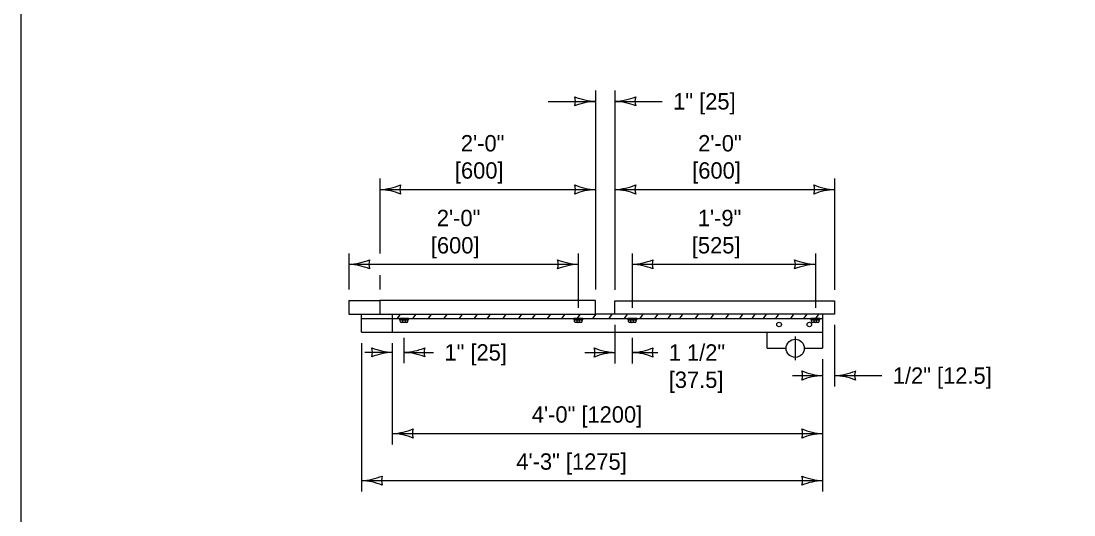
# Model space of a CAD drawing. Extents: x 49991.4 to 50021, y 49987.6 to 50011.4.
# Drawn here: x 49999.384 to 50003.247, y 49992.347 to 49994.159 of the extents above; entities that cross this region are included whole.
import ezdxf

# ---------------------------------------------------------------- set-up
doc = ezdxf.new("R2010")
doc.units = 0
for name, color, linetype in [('Level 1', 7, 'Continuous'), ('Level 2', 7, 'Continuous'), ('Level 3', 7, 'Continuous'), ('Level 4', 7, 'Continuous'), ('Level 5', 7, 'Continuous')]:
    doc.layers.add(name, color=color, linetype=linetype)

msp = doc.modelspace()

# ---------------------------------------------------------------- linework, layer by layer
at = {"layer": 'Level 1'}
for p, q in [((50000.7462, 49993.0166), (50000.7462, 49993.0836)), ((50000.7648, 49993.0669), (50000.7761, 49993.0836)), ((50000.8216, 49993.0669), (50000.8329, 49993.0836)), ((50000.8785, 49993.0669), (50000.8898, 49993.0836)), ((50000.9354, 49993.0669), (50000.9467, 49993.0836)), ((50000.9922, 49993.0669), (50001.0035, 49993.0836)), ((50001.0471, 49993.0669), (50001.0584, 49993.0836)), ((50001.0952, 49993.0669), (50001.1065, 49993.0836)), ((50001.1521, 49993.0669), (50001.1634, 49993.0836)), ((50001.2099, 49993.0669), (50001.2212, 49993.0836)), ((50001.2603, 49993.0669), (50001.2716, 49993.0836)), ((50001.3157, 49993.0669), (50001.327, 49993.0836)), ((50001.3683, 49993.0669), (50001.3795, 49993.0836)), ((50001.4245, 49993.0669), (50001.4359, 49993.0836)), ((50001.4819, 49993.0669), (50001.4932, 49993.0836)), ((50001.5627, 49993.0836), (50001.4909, 49993.0836)), ((50001.5409, 49993.0669), (50001.5522, 49993.0836)), ((50001.5978, 49993.0669), (50001.6091, 49993.0836)), ((50001.6546, 49993.0669), (50001.6659, 49993.0836)), ((50001.7095, 49993.0669), (50001.7209, 49993.0836)), ((50001.7576, 49993.0669), (50001.7689, 49993.0836)), ((50001.8007, 49993.0669), (50001.8119, 49993.0836)), ((50001.8576, 49993.0669), (50001.8688, 49993.0836)), ((50001.9144, 49993.0669), (50001.9256, 49993.0836)), ((50001.9693, 49993.0669), (50001.9805, 49993.0836)), ((50002.0202, 49993.0669), (50002.0314, 49993.0836)), ((50002.0656, 49993.0669), (50002.0769, 49993.0836)), ((50002.1079, 49993.0669), (50002.1191, 49993.0836)), ((50002.1531, 49993.0669), (50002.1643, 49993.0836)), ((50002.208, 49993.0669), (50002.2193, 49993.0836)), ((50002.256, 49993.0669), (50002.2673, 49993.0836)), ((50002.2991, 49993.0669), (50002.3104, 49993.0836)), ((50002.3244, 49993.0836), (50002.3244, 49992.958)), ((50000.7462, 49993.0669), (50002.3244, 49993.0669)), ((50000.7751, 49993.0559), (50000.7751, 49993.0622)), ((50000.7777, 49993.0533), (50000.8003, 49993.0533)), ((50000.7843, 49993.0558), (50000.7843, 49993.0622)), ((50000.7935, 49993.0558), (50000.7935, 49993.0622)), ((50000.8028, 49993.0559), (50000.8028, 49993.0622)), ((50001.4144, 49993.0559), (50001.4144, 49993.0622)), ((50001.417, 49993.0533), (50001.4396, 49993.0533)), ((50001.4236, 49993.0558), (50001.4236, 49993.0622)), ((50001.4328, 49993.0558), (50001.4328, 49993.0622)), ((50001.4421, 49993.0559), (50001.4421, 49993.0622)), ((50001.6122, 49993.0559), (50001.6122, 49993.0622)), ((50001.6148, 49993.0533), (50001.6374, 49993.0533)), ((50001.6214, 49993.0558), (50001.6214, 49993.0622)), ((50001.6306, 49993.0558), (50001.6306, 49993.0622)), ((50001.6399, 49993.0559), (50001.6399, 49993.0622)), ((50002.2842, 49993.0559), (50002.2842, 49993.0622)), ((50002.2868, 49993.0533), (50002.3094, 49993.0533)), ((50002.2934, 49993.0558), (50002.2934, 49993.0622)), ((50002.3026, 49993.0558), (50002.3026, 49993.0622)), ((50002.3119, 49993.0559), (50002.3119, 49993.0622)), ((50000.7462, 49993.0166), (50002.1217, 49993.0166)), ((50002.1217, 49993.0166), (50002.3244, 49993.0166)), ((50002.1217, 49992.958), (50002.1217, 49993.0166)), ((50002.1217, 49992.958), (50002.1907, 49992.958)), ((50002.2572, 49992.958), (50002.3244, 49992.958))]:
    msp.add_line(p, q, dxfattribs=at)
for points in [[(49999.3835, 49998.9992), (50016.7501, 49998.9992), (50016.7501, 49987.7988), (49999.3835, 49987.7988)], [(50000.7001, 49993.1336), (50000.7001, 49993.0836), (50001.4909, 49993.0836), (50001.4909, 49993.1336)], [(50002.3687, 49993.1326), (50002.3687, 49993.0836), (50001.5627, 49993.0836), (50001.5627, 49993.1326)], [(50000.7724, 49993.0669), (50000.7724, 49993.0622), (50000.8052, 49993.0622), (50000.8052, 49993.0669)], [(50001.4117, 49993.0669), (50001.4117, 49993.0622), (50001.4445, 49993.0622), (50001.4445, 49993.0669)], [(50001.6095, 49993.0669), (50001.6095, 49993.0622), (50001.6423, 49993.0622), (50001.6423, 49993.0669)], [(50002.2815, 49993.0669), (50002.2815, 49993.0622), (50002.3143, 49993.0622), (50002.3143, 49993.0669)]]:
    msp.add_lwpolyline(points, close=True, dxfattribs=at)
for centre, radius in [((50002.1648, 49993.0453), 0.00843), ((50002.2759, 49993.0453), 0.00843), ((50002.224, 49992.958), 0.0333)]:
    msp.add_circle(centre, radius, dxfattribs=at)
for centre, start, end in [((50000.7777, 49993.0558), 180, 270), ((50000.7818, 49993.0558), 270, 0), ((50000.7869, 49993.0558), 180, 270), ((50000.791, 49993.0558), 270, 0), ((50000.7961, 49993.0558), 180, 270), ((50000.8002, 49993.0558), 270, 0), ((50001.417, 49993.0558), 180, 270), ((50001.4211, 49993.0558), 270, 0), ((50001.4262, 49993.0558), 180, 270), ((50001.4303, 49993.0558), 270, 0), ((50001.4354, 49993.0558), 180, 270), ((50001.4395, 49993.0558), 270, 0), ((50001.6148, 49993.0558), 180, 270), ((50001.6189, 49993.0558), 270, 0), ((50001.624, 49993.0558), 180, 270), ((50001.6281, 49993.0558), 270, 0), ((50001.6332, 49993.0558), 180, 270), ((50001.6373, 49993.0558), 270, 0), ((50002.2868, 49993.0558), 180, 270), ((50002.2909, 49993.0558), 270, 0), ((50002.296, 49993.0558), 180, 270), ((50002.3001, 49993.0558), 270, 0), ((50002.3052, 49993.0558), 180, 270), ((50002.3093, 49993.0558), 270, 0)]:
    msp.add_arc(centre, 0.00257, start, end, dxfattribs=at)
at = {"layer": 'Level 3'}
for p, q in [((50001.4909, 49993.9042), (50001.4909, 49993.1736)), ((50001.5627, 49993.9042), (50001.5627, 49993.1726)), ((50001.3175, 49993.8642), (50001.4909, 49993.8642)), ((50001.5627, 49993.8642), (50001.7361, 49993.8642)), ((50000.7001, 49993.5805), (50000.7001, 49993.3061)), ((50002.3687, 49993.5805), (50002.3687, 49993.1726)), ((50000.7001, 49993.5405), (50001.4909, 49993.5405)), ((50001.5627, 49993.5405), (50002.3687, 49993.5405)), ((50000.5865, 49993.3061), (50000.5865, 49993.1736)), ((50001.4281, 49993.3061), (50001.4281, 49993.1069)), ((50001.6259, 49993.3061), (50001.6259, 49993.1069)), ((50002.2979, 49993.3061), (50002.2979, 49993.1069)), ((50000.5865, 49993.2661), (50001.4281, 49993.2661)), ((50001.6259, 49993.2661), (50002.2979, 49993.2661)), ((50000.7001, 49993.2261), (50000.7001, 49993.1736)), ((50001.5627, 49993.0436), (50001.5627, 49992.9026)), ((50002.3687, 49993.0436), (50002.3687, 49992.8179)), ((50000.6326, 49992.9766), (50000.6326, 49992.4325)), ((50000.7462, 49992.6052), (50000.7462, 49992.9766)), ((50000.789, 49992.903), (50000.789, 49992.9962)), ((50001.6261, 49992.9962), (50001.6261, 49992.9026)), ((50000.6446, 49992.9432), (50000.7462, 49992.9432)), ((50000.789, 49992.943), (50000.8969, 49992.943)), ((50001.4524, 49992.9426), (50001.5627, 49992.9426)), ((50001.6261, 49992.9426), (50001.72, 49992.9426)), ((50002.3244, 49992.918), (50002.3244, 49992.4325)), ((50002.2135, 49992.8581), (50002.3244, 49992.8581)), ((50002.3687, 49992.8579), (50002.5421, 49992.8579)), ((50000.7462, 49992.6452), (50002.3244, 49992.6452)), ((50000.6326, 49992.4725), (50002.3244, 49992.4725))]:
    msp.add_line(p, q, dxfattribs=at)
for centre, radius, start, end in [((50001.5001, 49994.0863), 0.2223, 247.456, 267.6395), ((50001.3627, 49993.8642), 0.0548, 342.1388, 17.8612), ((50001.5024, 49993.6315), 0.233, 92.8273, 112.0772), ((50001.5512, 49994.0969), 0.233, 272.8273, 292.0772), ((50001.5535, 49993.6421), 0.2223, 67.456, 87.6395), ((50001.6909, 49993.8642), 0.0548, 162.1388, 197.8612), ((50000.6886, 49993.7732), 0.233, 272.8273, 292.0772), ((50000.8283, 49993.5405), 0.0548, 162.1388, 197.8612), ((50001.5001, 49993.7626), 0.2223, 247.456, 267.6395), ((50001.3627, 49993.5405), 0.0548, 342.1388, 17.8612), ((50001.5512, 49993.7732), 0.233, 272.8273, 292.0772), ((50001.6909, 49993.5405), 0.0548, 162.1388, 197.8612), ((50002.3779, 49993.7626), 0.2223, 247.456, 267.6395), ((50002.2405, 49993.5405), 0.0548, 342.1388, 17.8612), ((50000.6909, 49993.3184), 0.2223, 67.456, 87.6395), ((50001.5024, 49993.3078), 0.233, 92.8273, 112.0772), ((50001.5535, 49993.3184), 0.2223, 67.456, 87.6395), ((50002.3802, 49993.3078), 0.233, 92.8273, 112.0772), ((50000.575, 49993.4988), 0.233, 272.8273, 292.0772), ((50000.7147, 49993.2661), 0.0548, 162.1388, 197.8612), ((50001.4373, 49993.4882), 0.2223, 247.456, 267.6395), ((50001.2999, 49993.2661), 0.0548, 342.1388, 17.8612), ((50001.6144, 49993.4988), 0.233, 272.8273, 292.0772), ((50001.7541, 49993.2661), 0.0548, 162.1388, 197.8612), ((50002.3071, 49993.4882), 0.2223, 247.456, 267.6395), ((50002.1697, 49993.2661), 0.0548, 342.1388, 17.8612), ((50000.5773, 49993.044), 0.2223, 67.456, 87.6395), ((50001.4396, 49993.0334), 0.233, 92.8273, 112.0772), ((50001.6167, 49993.044), 0.2223, 67.456, 87.6395), ((50002.3094, 49993.0334), 0.233, 92.8273, 112.0772), ((50000.7554, 49993.1653), 0.2223, 247.456, 267.6395), ((50000.618, 49992.9432), 0.0548, 342.1388, 17.8612), ((50000.7577, 49992.7105), 0.233, 92.8273, 112.0772), ((50000.7775, 49993.1757), 0.233, 272.8273, 292.0772), ((50000.7798, 49992.7209), 0.2223, 67.456, 87.6395), ((50000.9172, 49992.943), 0.0548, 162.1388, 197.8612), ((50001.5719, 49993.1647), 0.2223, 247.456, 267.6395), ((50001.4345, 49992.9426), 0.0548, 342.1388, 17.8612), ((50001.5742, 49992.7099), 0.233, 92.8273, 112.0772), ((50001.6146, 49993.1753), 0.233, 272.8273, 292.0772), ((50001.6169, 49992.7205), 0.2223, 67.456, 87.6395), ((50001.7543, 49992.9426), 0.0548, 162.1388, 197.8612), ((50002.3336, 49993.0802), 0.2223, 247.456, 267.6395), ((50002.1962, 49992.8581), 0.0548, 342.1388, 17.8612), ((50002.3359, 49992.6254), 0.233, 92.8273, 112.0772), ((50002.3572, 49993.0906), 0.233, 272.8273, 292.0772), ((50002.3595, 49992.6358), 0.2223, 67.456, 87.6395), ((50002.4969, 49992.8579), 0.0548, 162.1388, 197.8612), ((50000.7347, 49992.8779), 0.233, 272.8273, 292.0772), ((50000.8744, 49992.6452), 0.0548, 162.1388, 197.8612), ((50002.3336, 49992.8673), 0.2223, 247.456, 267.6395), ((50002.1962, 49992.6452), 0.0548, 342.1388, 17.8612), ((50000.737, 49992.4231), 0.2223, 67.456, 87.6395), ((50002.3359, 49992.4125), 0.233, 92.8273, 112.0772), ((50000.6211, 49992.7052), 0.233, 272.8273, 292.0772), ((50000.6234, 49992.2504), 0.2223, 67.456, 87.6395), ((50000.7608, 49992.4725), 0.0548, 162.1388, 197.8612), ((50002.3336, 49992.6946), 0.2223, 247.456, 267.6395), ((50002.1962, 49992.4725), 0.0548, 342.1388, 17.8612), ((50002.3359, 49992.2398), 0.233, 92.8273, 112.0772)]:
    msp.add_arc(centre, radius, start, end, dxfattribs=at)
at = {"layer": 'Level 4'}
for p, q in [((50000.5865, 49993.1336), (50000.7001, 49993.1336)), ((50000.5865, 49993.1336), (50000.5865, 49993.0836)), ((50000.5865, 49993.0836), (50000.7001, 49993.0836)), ((50000.6326, 49993.0166), (50000.6326, 49993.0836)), ((50000.6326, 49993.0669), (50000.7462, 49993.0669)), ((50000.6326, 49993.0166), (50000.7462, 49993.0166))]:
    msp.add_line(p, q, dxfattribs=at)
at = {"layer": 'Level 5'}
msp.add_line((50002.2239, 49993.0013), (50002.2239, 49992.9148), dxfattribs=at)

# ---------------------------------------------------------------- texts
at = {"layer": 'Level 2'}
for s, p in [('1" [25]', (50001.7761, 49993.8342)), ('2\'-0"', (50000.9972, 49993.6805)), ('2\'-0"', (50001.8678, 49993.6805)), ('[600]', (50000.9754, 49993.5805)), ('[600]', (50001.8461, 49993.5805)), ('2\'-0"', (50000.909, 49993.4061)), ('1\'-9"', (50001.8665, 49993.4061)), ('[600]', (50000.8872, 49993.3061)), ('[525]', (50001.8448, 49993.3061)), ('1" [25]', (50000.9369, 49992.913)), ('1 1/2"', (50001.76, 49992.9126)), ('1/2" [12.5]', (50002.5821, 49992.8279)), ('[37.5]', (50001.76, 49992.8126)), ('4\'-0" [1200]', (50001.2575, 49992.6852)), ('4\'-3" [1275]', (50001.2007, 49992.5125))]:
    msp.add_text(s, height=0.06, dxfattribs=at).set_placement(p)

doc.saveas('drawing.dxf')
